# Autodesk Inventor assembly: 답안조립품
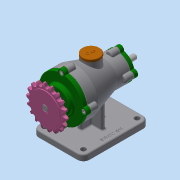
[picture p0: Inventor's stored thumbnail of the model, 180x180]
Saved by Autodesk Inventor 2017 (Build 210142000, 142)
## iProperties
Part Number: 답안조립품
Material: 일반
Document SubType Name: Assembly
Designer: mrc
Author: mrc
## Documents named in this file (15)
- C:\Users\mrc\Desktop\701206V1036\답안조립품.iam
- C:\Users\mrc\Desktop\701206V1036\본체.ipt
- C:\Users\mrc\Desktop\701206V1036\개스킷 B.ipt
- C:\Users\mrc\Desktop\701206V1036\개스킷 A.ipt
- C:\Users\mrc\Desktop\701206V1036\뒤커버.ipt
- C:\Users\mrc\Desktop\701206V1036\마개.ipt
- C:\Users\mrc\Desktop\701206V1036\베어링 6200.ipt
- C:\Users\mrc\Desktop\701206V1036\베어링 6203.ipt
- C:\Users\mrc\Desktop\701206V1036\오일 실 10 20 7.ipt
- C:\Users\mrc\Desktop\701206V1036\오일 실 17 30 8.ipt
- C:\Users\mrc\Desktop\701206V1036\축.ipt
- C:\Users\mrc\Desktop\701206V1036\키 4x4x14.ipt
- C:\Users\mrc\Desktop\701206V1036\앞커버.ipt
- C:\Users\mrc\Desktop\701206V1036\스프로킷.ipt
- C:\Users\mrc\Desktop\701206V1036\볼트 M5.ipt
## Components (2 placed, 2 different names)
1. 개스킷 B:1
2. 개스킷 A:1
